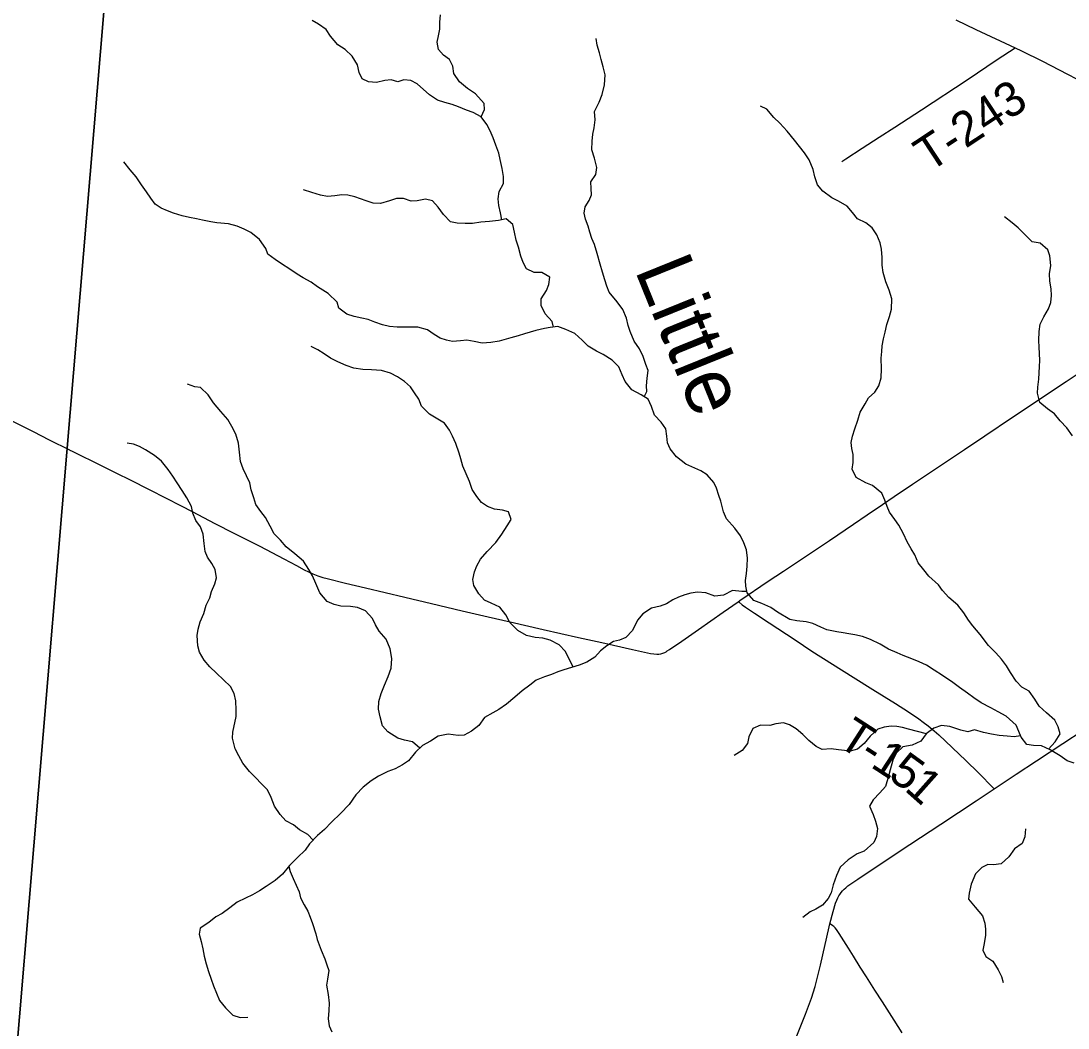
# Model space of a CAD drawing. Extents: x 0 to 1101, y 0 to 440.
# Drawn here: x 847.707 to 849.429, y 379.041 to 380.696 of the extents above; entities that cross this region are included whole.
import ezdxf

# ---------------------------------------------------------------- set-up
doc = ezdxf.new("R2010")
doc.units = 0
for name, color, linetype in [('GM_X_County_Road', 7, 'Continuous'), ('GM_X_Minor_River', 7, 'Continuous'), ('GM_X_Minor_River_Text', 7, 'Continuous'), ('GM_X_State_Route', 7, 'Continuous'), ('GM_X_Township_Road', 7, 'Continuous'), ('GM_X_Township_Road_Text', 7, 'Continuous')]:
    doc.layers.add(name, color=color, linetype=linetype)

msp = doc.modelspace()

# ---------------------------------------------------------------- linework, layer by layer
at = {"layer": 'GM_X_County_Road'}
for points in [[(847.5335, 377.0456), (847.6089, 377.9284), (847.6897, 378.8763), (847.7828, 379.9871), (847.8653, 380.9722), (847.896, 381.3391), (846.8323, 381.427), (846.7789, 381.4314), (846.7617, 381.4329), (846.7534, 381.4335), (845.8327, 381.5116), (845.7218, 381.5239), (845.7047, 381.5258), (845.3492, 381.569), (845.0655, 381.6042), (845.008, 381.6114), (844.8229, 381.6343), (844.8107, 381.6358), (844.7738, 381.6404), (844.7118, 381.648), (844.0658, 381.7282)], [(849.2447, 380.6979), (849.2778, 380.682), (849.3424, 380.6517), (849.3528, 380.6469), (849.3872, 380.6295), (849.4845, 380.5796)]]:
    msp.add_lwpolyline(points, dxfattribs=at)
msp.add_lwpolyline([(850.9258, 375.8797), (850.9258, 381.1617), (850.8488, 381.1661), (850.84, 381.1666), (850.8316, 381.167), (850.794, 381.1689), (850.7928, 381.169), (849.9699, 381.2155), (849.9584, 381.2161), (849.5879, 381.237), (848.2076, 381.3203), (847.9626, 381.3347), (847.896, 381.3391), (847.8653, 380.9722), (847.7828, 379.9871), (847.6897, 378.8763), (847.6089, 377.9284), (847.5335, 377.0456), (847.5303, 377.0082), (847.4662, 376.2566), (847.7946, 376.221), (849.0627, 376.0925), (849.9034, 375.9956), (850.1463, 375.9688)], close=True, dxfattribs=at)
at = {"layer": 'GM_X_Minor_River'}
for points in [[(848.4982, 380.3692), (848.4961, 380.3804), (848.4933, 380.3926), (848.4923, 380.4036), (848.494, 380.4154), (848.5007, 380.4286), (848.5008, 380.4403), (848.4988, 380.4533), (848.4952, 380.4681), (848.4931, 380.4784), (848.4883, 380.4917), (848.484, 380.5036), (848.4788, 380.5154), (848.4733, 380.5258), (848.4643, 380.5384), (848.4512, 380.5455), (848.4402, 380.5491), (848.427, 380.5546), (848.4164, 380.5585), (848.4043, 380.5618), (848.3922, 380.5654), (848.3794, 380.5747), (848.3591, 380.5925), (848.3486, 380.5979), (848.3372, 380.5989), (848.3269, 380.5956), (848.3163, 380.5992), (848.3056, 380.5978), (848.2923, 380.5946), (848.279, 380.596), (848.2684, 380.6007), (848.2633, 380.6114), (848.2608, 380.624), (848.2523, 380.6378), (848.2403, 380.649), (848.2286, 380.6567), (848.2163, 380.6706), (848.2092, 380.6817), (848.1968, 380.6907), (848.1863, 380.6965)], [(848.4643, 380.5384), (848.4695, 380.5501), (848.4689, 380.5604), (848.4547, 380.5762), (848.4415, 380.5851), (848.4284, 380.5959), (848.4191, 380.6097), (848.4177, 380.6215), (848.4122, 380.6326), (848.402, 380.6396), (848.3938, 380.6492), (848.3921, 380.661), (848.3938, 380.6716), (848.3962, 380.6826), (848.3964, 380.6936), (848.3974, 380.7057)], [(848.7322, 380.0783), (848.7367, 380.0867), (848.7361, 380.0962), (848.7371, 380.1087), (848.7388, 380.1212), (848.7351, 380.1311), (848.7308, 380.1441), (848.7245, 380.1567), (848.7156, 380.1698), (848.709, 380.1854), (848.7057, 380.1953), (848.7032, 380.2075), (848.697, 380.2217), (848.6881, 380.2343), (848.6746, 380.2501), (848.6706, 380.2597), (848.6673, 380.2703), (848.6637, 380.2829), (848.6598, 380.2959), (848.6547, 380.3134), (848.6504, 380.3283), (848.6463, 380.3382), (848.6431, 380.3485), (848.6402, 380.3588), (848.6358, 380.3699), (848.6337, 380.3802), (848.6354, 380.3904), (848.642, 380.4005), (848.6456, 380.4103), (848.6453, 380.4206), (848.6447, 380.4312), (848.6525, 380.4436), (848.6546, 380.455), (848.6503, 380.4706), (848.6463, 380.4843), (848.6469, 380.4984), (848.6479, 380.5098), (848.6499, 380.52), (848.6516, 380.5332), (848.6507, 380.5473), (848.6582, 380.5624), (848.6633, 380.5752), (848.667, 380.5911), (848.668, 380.6074), (848.6651, 380.6207), (848.6615, 380.6325), (848.6586, 380.6436), (848.655, 380.6562), (848.6533, 380.6672)], [(849.3974, 379.4992), (849.408, 379.5112), (849.4162, 379.5243), (849.413, 379.5358), (849.4074, 379.5465), (849.3939, 379.5585), (849.3816, 379.5696), (849.3749, 379.5811), (849.3656, 379.5942), (849.3536, 379.6008), (849.3442, 379.6108), (849.3346, 379.625), (849.3279, 379.6361), (849.3201, 379.6469), (849.3104, 379.6573), (849.2988, 379.6692), (849.285, 379.6873), (849.273, 379.7015), (849.2656, 379.7111), (849.2582, 379.723), (849.2481, 379.7357), (849.2331, 379.748), (849.223, 379.7596), (849.2163, 379.7692), (849.2002, 379.7835), (849.1924, 379.7935), (849.1831, 379.8054), (849.1772, 379.8184), (849.1713, 379.8283), (849.165, 379.8398), (849.1587, 379.8528), (849.151, 379.867), (849.1447, 379.8765), (849.1357, 379.8885), (849.1317, 379.898), (849.128, 379.9083), (849.1233, 379.9198), (849.1075, 379.9325), (849.0969, 379.9369), (849.0811, 379.9455), (849.0745, 379.9592), (849.0762, 379.9702), (849.076, 379.9835), (849.0739, 379.993), (849.0725, 380.0029), (849.0746, 380.0135), (849.0789, 380.0256), (849.0837, 380.0395), (849.0874, 380.0531), (849.0955, 380.0667), (849.1014, 380.0765), (849.1114, 380.0858), (849.1184, 380.0963), (849.122, 380.1092), (849.1223, 380.1243), (849.1222, 380.1414), (849.1231, 380.1524), (849.1236, 380.1619), (849.1261, 380.1736), (849.1285, 380.1846), (849.1314, 380.1971), (849.1358, 380.2099), (849.139, 380.2224), (849.1396, 380.2391), (849.1349, 380.2536), (849.1298, 380.2673), (849.1251, 380.2822), (849.1234, 380.2947), (849.1236, 380.3073), (849.1223, 380.3209), (849.1202, 380.3312), (849.1147, 380.3446), (849.1072, 380.3557), (849.0967, 380.3638), (849.0831, 380.3709), (849.0746, 380.3813), (849.066, 380.3913), (849.052, 380.3995), (849.0411, 380.4053), (849.0261, 380.4162), (849.0171, 380.4266), (849.0131, 380.4399), (849.0103, 380.4517), (849.0037, 380.4674), (848.9959, 380.4789), (848.9877, 380.4893), (848.9795, 380.5), (848.9675, 380.5146), (848.9552, 380.5277), (848.9455, 380.5374), (848.9339, 380.5508), (848.9237, 380.5559)], [(848.1951, 380.2587), (848.1846, 380.2665), (848.1714, 380.2739), (848.1616, 380.2798), (848.1481, 380.2891), (848.1372, 380.2957), (848.1255, 380.3039), (848.1135, 380.3124), (848.1102, 380.3219), (848.0998, 380.3365), (848.0852, 380.3481), (848.0742, 380.3536), (848.0629, 380.3587), (848.0489, 380.3624), (848.0295, 380.3642), (848.0197, 380.3659), (848.006, 380.3684), (847.9958, 380.3708), (847.9844, 380.3729), (847.9727, 380.3753), (847.9583, 380.3797), (847.9485, 380.3837), (847.9379, 380.3884), (847.9282, 380.3946), (847.9207, 380.4046), (847.914, 380.415), (847.9055, 380.4265), (847.8969, 380.4395), (847.8872, 380.4514), (847.8768, 380.4641)], [(848.5833, 380.1928), (848.5808, 380.2019), (848.5696, 380.2146), (848.5629, 380.2283), (848.5631, 380.2393), (848.5717, 380.2529), (848.5753, 380.2627), (848.577, 380.2748), (848.5642, 380.2826), (848.5512, 380.2824), (848.5388, 380.2887), (848.5332, 380.2986), (848.5292, 380.3093), (848.5257, 380.3238), (848.5217, 380.3356), (848.5188, 380.3486), (848.516, 380.3611), (848.5051, 380.3708), (848.4929, 380.3679), (848.478, 380.3663), (848.4636, 380.3654), (848.4502, 380.3629), (848.4377, 380.3627), (848.4248, 380.3633), (848.4138, 380.3658), (848.4022, 380.3777), (848.3933, 380.3896), (848.3843, 380.4004), (848.3726, 380.4028), (848.3592, 380.4), (848.349, 380.3998), (848.3365, 380.4038), (848.3251, 380.4043), (848.3132, 380.4), (848.2987, 380.396), (848.2866, 380.3962), (848.2749, 380.4002), (848.2563, 380.4066), (848.245, 380.4094), (848.2351, 380.4103), (848.2233, 380.4086), (848.2115, 380.4076), (848.2001, 380.4097), (848.1857, 380.4137), (848.1721, 380.4181)], [(849.4364, 380.0139), (849.4271, 380.0274), (849.4166, 380.0389), (849.4069, 380.0501), (849.3957, 380.0586), (849.3829, 380.069), (849.3789, 380.0839), (849.3799, 380.0938), (849.3812, 380.107), (849.3817, 380.1173), (849.3823, 380.1279), (849.3828, 380.1377), (849.3826, 380.1491), (849.382, 380.1598), (849.3814, 380.1704), (849.382, 380.1852), (849.3837, 380.1977), (849.3896, 380.2097), (849.397, 380.2225), (849.401, 380.2331), (849.4023, 380.2448), (849.4014, 380.2555), (849.3993, 380.2681), (849.3991, 380.2802), (849.4008, 380.2938), (849.3992, 380.3098), (849.3963, 380.3197), (849.3835, 380.3309), (849.3702, 380.333), (849.3579, 380.3457), (849.3474, 380.3558), (849.3373, 380.3639), (849.3249, 380.374)], [(849.2509, 379.6001), (849.2397, 379.6083), (849.2228, 379.6203), (849.2092, 379.6289), (849.1964, 379.637), (849.1843, 379.6425), (849.1722, 379.6477), (849.1583, 379.6532), (849.1485, 379.6571), (849.1341, 379.6634), (849.1206, 379.6716), (849.1043, 379.6791), (849.0915, 379.6842), (849.0786, 379.6871), (849.0691, 379.6884), (849.0597, 379.69), (849.049, 379.6921), (849.0328, 379.6954), (849.0229, 379.6997), (849.0094, 379.7056), (848.9984, 379.7081), (848.9832, 379.7098), (848.9718, 379.7119), (848.9515, 379.7244), (848.9406, 379.7321), (848.9255, 379.7384), (848.9126, 379.7432), (848.9014, 379.7559), (848.8993, 379.7669), (848.8991, 379.7764), (848.9004, 379.7878), (848.9014, 379.7995), (848.9023, 379.8128), (848.9006, 379.8265), (848.8963, 379.8379), (848.8907, 379.8494), (848.8811, 379.8624), (848.8676, 379.8778), (848.8625, 379.8893), (848.8586, 379.9064), (848.8553, 379.916), (848.8513, 379.9278), (848.8469, 379.9374), (848.8361, 379.9501), (848.8255, 379.9567), (848.8108, 379.9633), (848.801, 379.9673), (848.7856, 379.9797), (848.7748, 379.9928), (848.7707, 380.0027), (848.7698, 380.0137), (848.7681, 380.0255), (848.7603, 380.0366), (848.749, 380.0482), (848.7443, 380.0623), (848.7388, 380.0745), (848.7271, 380.0812), (848.7117, 380.0898), (848.7009, 380.1032), (848.6961, 380.1143), (848.6906, 380.1273), (848.6797, 380.1385), (848.6651, 380.1474), (848.6537, 380.1529), (848.6402, 380.1611), (848.6301, 380.1711), (848.6185, 380.1819), (848.6034, 380.1886), (848.5905, 380.1937), (848.5776, 380.192), (848.5681, 380.1903), (848.5539, 380.1871), (848.5352, 380.1817), (848.5249, 380.1784), (848.5131, 380.1748), (848.4936, 380.1694), (848.4803, 380.1674), (848.4658, 380.1665), (848.4526, 380.1689), (848.4408, 380.171), (848.4302, 380.1701), (848.4168, 380.1691), (848.407, 380.1712), (848.3968, 380.1744), (848.387, 380.1806), (848.3757, 380.188), (848.3598, 380.1928), (848.3473, 380.1926), (848.337, 380.1928), (848.326, 380.1926), (848.3135, 380.1935), (848.3021, 380.1963), (848.2893, 380.2007), (848.2783, 380.2051), (848.2681, 380.2071), (848.2552, 380.21), (848.2431, 380.214), (848.2303, 380.2237), (848.2271, 380.2336), (848.2128, 380.2478), (848.1951, 380.2587)], [(848.6155, 379.634), (848.6027, 379.6596), (848.5923, 379.6704), (848.5779, 379.6782), (848.5654, 379.6814), (848.5529, 379.6828), (848.5389, 379.686), (848.5246, 379.6942), (848.5115, 379.7073), (848.5049, 379.7196), (848.4948, 379.7323), (848.4805, 379.7389), (848.4699, 379.744), (848.4606, 379.7544), (848.4524, 379.7678), (848.4507, 379.7781), (848.4535, 379.7906), (848.4571, 379.8004), (848.4633, 379.8113), (848.4742, 379.824), (848.4885, 379.8386), (848.4982, 379.8525), (848.5068, 379.866), (848.5138, 379.8762), (848.5094, 379.8888), (848.4992, 379.8916), (848.4863, 379.8933), (848.4746, 379.8976), (848.4648, 379.9046), (848.4573, 379.9142), (848.4495, 379.9257), (848.4448, 379.9391), (848.4397, 379.9517), (848.4338, 379.9643), (848.4309, 379.9761), (848.4281, 379.9857), (848.4226, 380.0013), (848.4171, 380.0135), (848.4119, 380.0235), (848.4041, 380.035), (848.3928, 380.0416), (848.3793, 380.0494), (848.3658, 380.0625), (848.3618, 380.074), (848.3547, 380.0847), (848.348, 380.0943), (848.3379, 380.1032), (848.3266, 380.111), (848.3149, 380.1168), (848.3002, 380.1212), (848.2839, 380.1226), (848.2694, 380.1229), (848.2546, 380.125), (848.2422, 380.1294), (848.2286, 380.1356), (848.2165, 380.1419), (848.206, 380.1485), (848.1958, 380.1551), (848.1845, 380.161)], [(848.3635, 379.5009), (848.3511, 379.511), (848.3382, 379.5139), (848.3269, 379.5171), (848.3107, 379.5276), (848.3021, 379.5372), (848.2981, 379.5524), (848.2953, 379.5646), (848.2959, 379.5775), (848.2995, 379.5907), (848.305, 379.6043), (848.3113, 379.6186), (848.3161, 379.6322), (848.3175, 379.6478), (848.3147, 379.6637), (848.3077, 379.6798), (848.2962, 379.6929), (848.2902, 379.7036), (848.2855, 379.7139), (848.2739, 379.7262), (848.2607, 379.7321), (848.2493, 379.7335), (848.2333, 379.7341), (848.2224, 379.7365), (848.211, 379.7416), (848.1991, 379.7559), (848.1921, 379.7715), (848.187, 379.7838), (848.1807, 379.7945), (848.1718, 379.8079), (848.1575, 379.8203), (848.1436, 379.8315), (848.1343, 379.8426), (848.1238, 379.8531), (848.1172, 379.8653), (848.1094, 379.8795), (848.102, 379.8898), (848.0934, 379.9013), (848.0902, 379.912), (848.0858, 379.925), (848.0837, 379.9368), (848.0727, 379.9597), (848.0683, 379.9716), (848.0666, 379.9871), (848.065, 380.002), (848.0606, 380.0165), (848.054, 380.0295), (848.0473, 380.0406), (848.0361, 380.054), (848.0242, 380.0683), (848.0153, 380.0813), (848.0025, 380.0933), (847.9931, 380.0946), (847.981, 380.0989)], [(848.1877, 379.3494), (848.1792, 379.3585), (848.1652, 379.3663), (848.1555, 379.3745), (848.1431, 379.3811), (848.1337, 379.3915), (848.1241, 379.4053), (848.1186, 379.4194), (848.1127, 379.432), (848.0831, 379.4625), (848.0723, 379.4759), (848.0657, 379.4878), (848.0598, 379.4997), (848.0555, 379.5172), (848.056, 379.527), (848.061, 379.5528), (848.0615, 379.563), (848.0606, 379.5782), (848.0582, 379.5904), (848.0519, 379.6022), (848.0287, 379.6238), (848.0182, 379.6342), (848.0085, 379.6454), (848.0011, 379.6584), (847.9982, 379.6687), (847.9973, 379.6858), (847.9986, 379.696), (848.0022, 379.7085), (848.0081, 379.7221), (848.0122, 379.7357), (848.0177, 379.7477), (848.0209, 379.7579), (848.0264, 379.7707), (848.0292, 379.7805), (848.0268, 379.7942), (848.0212, 379.8042), (848.0142, 379.8146), (848.0105, 379.8241), (848.0088, 379.837), (848.0068, 379.8526), (848.0024, 379.8644), (847.995, 379.8748), (847.9898, 379.8867), (847.9877, 379.8981), (847.98, 379.9122), (847.9722, 379.9241), (847.964, 379.9368), (847.9569, 379.9475), (847.9495, 379.9586), (847.9383, 379.9721), (847.9271, 379.9814), (847.912, 379.9907), (847.9022, 379.9962), (847.8924, 380.0001), (847.8822, 380.0022)], [(848.901, 379.7584), (848.8931, 379.7583), (848.8776, 379.76), (848.8626, 379.7519), (848.8485, 379.7502), (848.8334, 379.7558), (848.8201, 379.7571), (848.8091, 379.7554), (848.7992, 379.7525), (848.7888, 379.7489), (848.7793, 379.7445), (848.7689, 379.7378), (848.7586, 379.7342), (848.7445, 379.731), (848.7299, 379.7217), (848.7214, 379.7109), (848.7131, 379.6939), (848.7023, 379.6823), (848.6916, 379.6783), (848.682, 379.6758), (848.6709, 379.6688), (848.6605, 379.6606), (848.6512, 379.6501), (848.6378, 379.642), (848.6252, 379.6369), (848.613, 379.6333), (848.6, 379.6293), (848.5904, 379.626), (848.5801, 379.6216), (848.5686, 379.618), (848.5545, 379.6126), (848.5441, 379.6044), (848.5314, 379.5951), (848.5195, 379.5843), (848.506, 379.5731), (848.4933, 379.5642), (848.4833, 379.5586), (848.4695, 379.5513), (848.4602, 379.5378), (848.4483, 379.5288), (848.4364, 379.5218), (848.4261, 379.5216), (848.4098, 379.5234), (848.3934, 379.5206), (848.3811, 379.5124), (848.3677, 379.5051), (848.3561, 379.4939), (848.3445, 379.48), (848.3349, 379.4733), (848.3226, 379.4667), (848.3108, 379.4623), (848.2951, 379.4546), (848.2832, 379.4468), (848.2701, 379.4368), (848.2581, 379.4237), (848.2469, 379.4083), (848.2329, 379.3933), (848.2183, 379.3788), (848.2063, 379.3672), (848.1951, 379.3571), (848.182, 379.3433), (848.1746, 379.3332), (848.1623, 379.3208), (848.1491, 379.3078), (848.1375, 379.2935), (848.1256, 379.2831), (848.1106, 379.2735), (848.0998, 379.266), (848.0879, 379.2598), (848.0765, 379.2543), (848.063, 379.2473), (848.0507, 379.2384), (848.038, 379.2287), (848.0281, 379.2232), (848.0161, 379.2139), (848.0023, 379.205), (848.0006, 379.1948), (848.0039, 379.1829), (848.0064, 379.1711), (848.0088, 379.1586), (848.0117, 379.1464), (848.0157, 379.1338), (848.02, 379.1208), (848.024, 379.1102), (848.0339, 379.0861), (848.0436, 379.0738), (848.056, 379.0618), (848.0681, 379.0579), (848.0806, 379.0584)], [(849.4394, 379.4762), (849.4281, 379.4797), (849.4164, 379.4883), (849.3998, 379.498), (849.3859, 379.5047), (849.3726, 379.5053), (849.3616, 379.5066), (849.3523, 379.5185), (849.3486, 379.528), (849.3442, 379.5384), (849.3277, 379.553), (849.3145, 379.5604), (849.3021, 379.5671), (849.2863, 379.5749), (849.2742, 379.5831), (849.2641, 379.5912), (849.2509, 379.6001)], [(849.1967, 379.5243), (849.167, 379.532), (849.1572, 379.5348), (849.1477, 379.5361), (849.1382, 379.5366), (849.1268, 379.5353), (849.1165, 379.532), (849.1041, 379.5205), (849.0941, 379.5081), (849.0833, 379.4988), (849.0711, 379.4956), (849.0616, 379.4969), (849.0517, 379.4981), (849.0396, 379.4995), (849.0251, 379.4986), (849.0149, 379.5033), (849.0029, 379.5133), (848.9932, 379.523), (848.9823, 379.5322), (848.971, 379.5392), (848.9612, 379.5424), (848.949, 379.5404), (848.9391, 379.5378), (848.9235, 379.5385), (848.9109, 379.533), (848.9046, 379.519), (848.9021, 379.5081), (848.8936, 379.4968), (848.8802, 379.4887)], [(849.3513, 379.5209), (849.3409, 379.5191), (849.3291, 379.5204), (849.3162, 379.5217), (849.3033, 379.5234), (849.2905, 379.5263), (849.2757, 379.5307), (849.2646, 379.5275), (849.2529, 379.5303), (849.2347, 379.5363), (849.2215, 379.538), (849.2089, 379.5336), (849.1962, 379.524), (849.1872, 379.5123), (849.1731, 379.5054), (849.1574, 379.5026), (849.147, 379.4929), (849.1411, 379.4808), (849.1367, 379.4653), (849.1343, 379.4544), (849.1291, 379.4377), (849.1198, 379.4273), (849.1086, 379.4157), (849.1031, 379.4051), (849.109, 379.3918), (849.1126, 379.3807), (849.1158, 379.3685), (849.1145, 379.3556), (849.1101, 379.3454), (849.0943, 379.3313), (849.0825, 379.3269), (849.0679, 379.3173), (849.0544, 379.305), (849.0485, 379.2914), (849.0429, 379.2759), (849.0397, 379.2631), (849.035, 379.2533), (849.0257, 379.2424), (849.0146, 379.2361), (849.005, 379.2317), (848.9934, 379.2221)], [(849.3594, 379.3681), (849.3581, 379.3549), (849.3537, 379.3439), (849.3414, 379.335), (849.3317, 379.3223), (849.3194, 379.3107), (849.3068, 379.309), (849.2973, 379.3095), (849.2877, 379.3047), (849.2769, 379.2943), (849.2698, 379.2769), (849.2666, 379.2626), (849.2656, 379.2527), (849.2768, 379.2392), (849.2884, 379.225), (849.2924, 379.2128), (849.2938, 379.2029), (849.2936, 379.1935), (849.2915, 379.1798), (849.2894, 379.1685), (849.2942, 379.1585), (849.3055, 379.1504), (849.3144, 379.1362), (849.3199, 379.1255), (849.3228, 379.1156)], [(848.1478, 379.3062), (848.1501, 379.2979), (848.1549, 379.2864), (848.16, 379.2753), (848.1648, 379.2643), (848.1673, 379.2547), (848.1732, 379.2429), (848.1791, 379.2326), (848.1831, 379.223), (848.1868, 379.2123), (848.1922, 379.1955), (848.1947, 379.186), (848.2013, 379.1688), (848.2071, 379.1543), (848.2104, 379.1448), (848.2137, 379.1353), (848.2116, 379.1212), (848.2099, 379.111), (848.2123, 379.0958), (848.2144, 379.0814), (848.2138, 379.0696), (848.2128, 379.0556), (848.2142, 379.0442), (848.2186, 379.0342)]]:
    msp.add_lwpolyline(points, dxfattribs=at)
at = {"layer": 'GM_X_State_Route'}
for points in [[(848.9823, 379.025), (848.9977, 379.0637), (849.0077, 379.0898), (849.0135, 379.1089), (849.0221, 379.1439), (849.0365, 379.2069), (849.0377, 379.2117), (849.0429, 379.2322), (849.047, 379.2458), (849.049, 379.2509), (849.0507, 379.2547), (849.0524, 379.2577), (849.0539, 379.2602), (849.056, 379.2632), (849.0586, 379.2663), (849.0612, 379.269), (849.0637, 379.2713), (849.0674, 379.2744), (849.0719, 379.2777), (849.0835, 379.2856), (849.1025, 379.298), (849.1691, 379.3423), (849.22, 379.3756), (849.278, 379.4141), (849.308, 379.4338), (849.3144, 379.438), (849.3443, 379.458), (849.3774, 379.4799), (849.421, 379.5085), (849.4542, 379.5304)], [(849.1567, 379.033), (849.1433, 379.0538), (849.1241, 379.0837), (849.1117, 379.1031), (849.0981, 379.1246), (849.0877, 379.1408), (849.0766, 379.1587), (849.0684, 379.1719), (849.0531, 379.196), (849.0488, 379.2025), (849.0463, 379.2055), (849.0443, 379.2074), (849.0425, 379.2088), (849.0404, 379.2101), (849.0377, 379.2117)]]:
    msp.add_lwpolyline(points, dxfattribs=at)
at = {"layer": 'GM_X_Township_Road'}
for points in [[(849.0573, 380.4647), (849.064, 380.4691), (849.091, 380.4867), (849.1185, 380.5047), (849.1447, 380.5214), (849.1884, 380.5498), (849.2637, 380.5993), (849.3126, 380.6323), (849.3424, 380.6517)], [(846.9593, 380.4123), (847.0194, 380.3819), (847.0494, 380.367), (847.0904, 380.3462), (847.1157, 380.3329), (847.1499, 380.3152), (847.1838, 380.2981), (847.2137, 380.2831), (847.2624, 380.2583), (847.3224, 380.227), (847.3621, 380.2065), (847.398, 380.188), (847.4308, 380.1704), (847.514, 380.127), (847.5356, 380.116), (847.5718, 380.0984), (847.5738, 380.0974), (847.5936, 380.0877), (847.633, 380.068), (847.6718, 380.0483), (847.7274, 380.0211), (847.754, 380.0075), (847.7873, 379.9908)], [(848.8871, 379.7414), (848.8897, 379.7433), (848.9364, 379.7753), (848.9613, 379.7917), (849.0368, 379.8419), (849.0764, 379.8686), (849.099, 379.8839), (849.1241, 379.9011), (849.1436, 379.9143), (849.1735, 379.9344), (849.2148, 379.962), (849.2593, 379.9916), (849.2927, 380.0142), (849.3381, 380.0447), (849.3768, 380.0706), (849.4006, 380.0864), (849.4265, 380.1035), (849.5263, 380.17)], [(847.7873, 379.9908), (847.7878, 379.9906), (847.7914, 379.9889)], [(847.7914, 379.9889), (847.7969, 379.9863), (847.8351, 379.9676), (847.8655, 379.9522), (847.8856, 379.9424), (847.9193, 379.9254), (847.9706, 379.899), (847.9888, 379.8897), (848.0261, 379.8701), (848.0577, 379.8541), (848.1003, 379.8324), (848.1399, 379.8118), (848.1605, 379.8007), (848.173, 379.7938), (848.1802, 379.7903), (848.1876, 379.7871), (848.1955, 379.7841), (848.204, 379.7812), (848.2111, 379.7793), (848.2411, 379.7716), (848.2738, 379.7639), (848.3385, 379.7486), (848.3824, 379.7383), (848.4332, 379.7264), (848.4756, 379.7167), (848.5118, 379.7081), (848.5663, 379.6958), (848.6245, 379.6828), (848.6626, 379.6741), (848.713, 379.663), (848.7425, 379.6565), (848.7481, 379.6557), (848.753, 379.6553), (848.7563, 379.6553), (848.7597, 379.6557), (848.7631, 379.6566), (848.7665, 379.658), (848.7683, 379.6591), (848.7703, 379.6604), (848.774, 379.6628), (848.794, 379.6764), (848.8214, 379.6959), (848.8623, 379.7241), (848.8871, 379.7414)], [(848.8871, 379.7414), (848.8883, 379.7404), (848.8934, 379.7362), (848.899, 379.7324), (848.9139, 379.7227), (848.9377, 379.7069), (848.9807, 379.6785), (849.0081, 379.6603), (849.0757, 379.6173), (849.1084, 379.5969), (849.1455, 379.5742), (849.1667, 379.5606), (849.1842, 379.5487), (849.1913, 379.5435), (849.1991, 379.5375), (849.2091, 379.5294), (849.2171, 379.5224), (849.2612, 379.4805), (849.2821, 379.4601), (849.307, 379.4349), (849.308, 379.4338)]]:
    msp.add_lwpolyline(points, dxfattribs=at)

# ---------------------------------------------------------------- texts
at = {"layer": 'GM_X_Minor_River_Text'}
msp.add_text('Little', height=0.09471, rotation=292.0221, dxfattribs=at).set_placement((848.7161, 380.287))
at = {"layer": 'GM_X_Township_Road_Text'}
for s, height, rotation, p in [('T-243', 0.05682, 33.3896, (849.2009, 380.4461)), ('T', 0.0568, 327.1551, (849.0475, 379.5065)), ('1', 0.0568, 326.8858, (849.1027, 379.4708)), ('-', 0.0568, 327.1067, (849.0832, 379.4834)), ('5', 0.0568, 323.9378, (849.1314, 379.4521)), ('1', 0.0568, 318.3431, (849.1586, 379.4324))]:
    msp.add_text(s, height=height, rotation=rotation, dxfattribs=at).set_placement(p)

doc.saveas('drawing.dxf')
